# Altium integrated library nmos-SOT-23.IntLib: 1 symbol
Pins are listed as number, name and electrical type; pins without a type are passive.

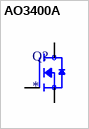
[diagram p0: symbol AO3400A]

## AO3400A
designator Q?
Trans MOSFET N-CH 30V 5.7A 3-Pin SOT-23; MP: AO3400A
footprint SOT95P280X125-3N
pins: 1 G, 2 S, 3 D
